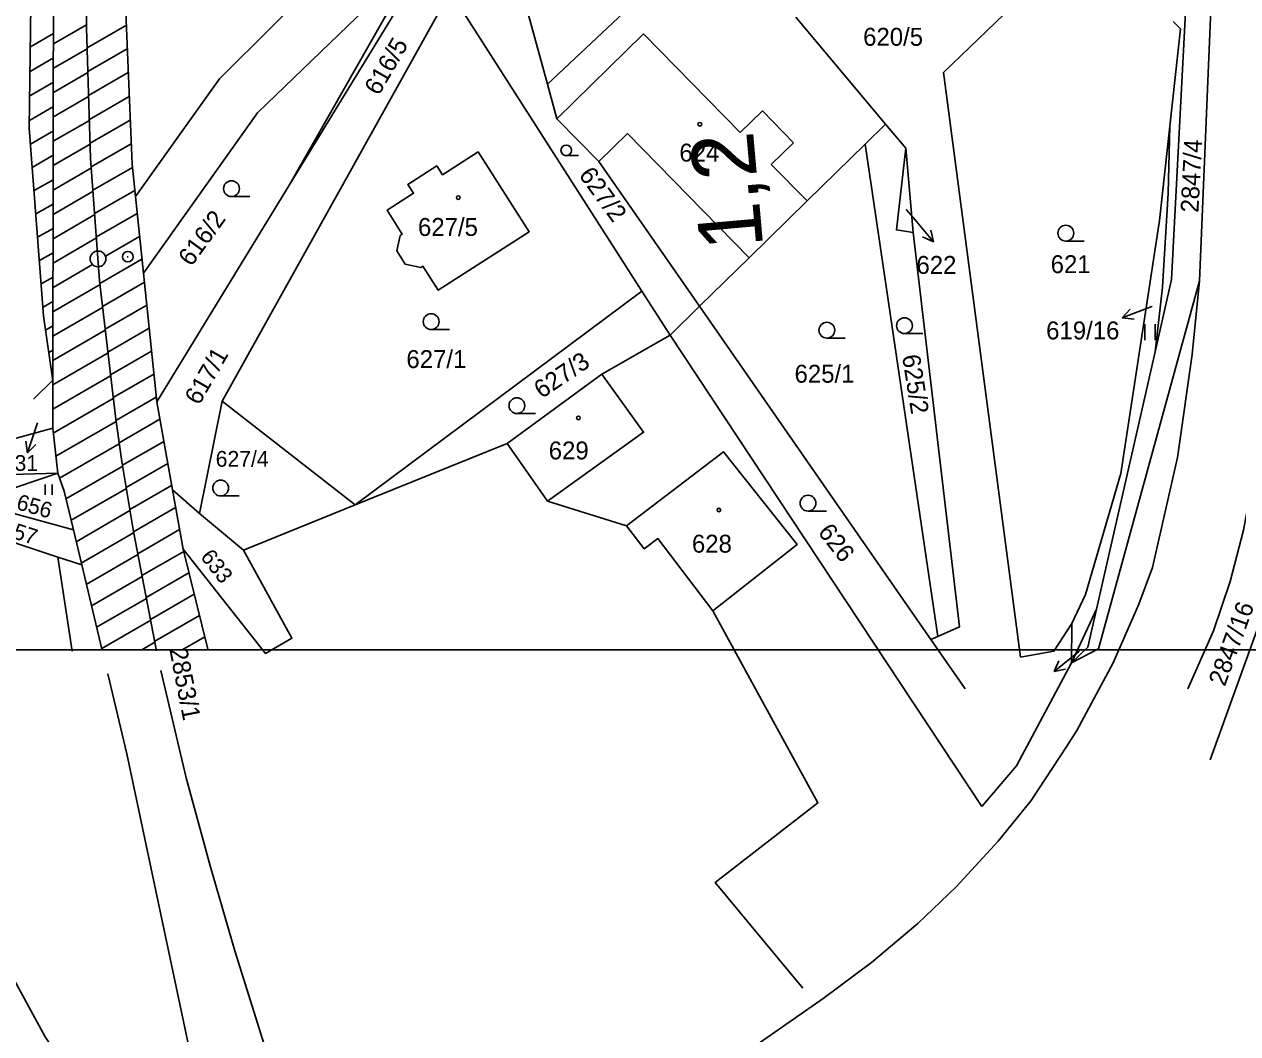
# Model space of a CAD drawing. Extents: x -558500 to -557517, y -1073973 to -1073051.
# Drawn here: x -558299.9 to -558184.7, y -1073820.5 to -1073724.7 of the extents above; entities that cross this region are included whole.
import ezdxf

# ---------------------------------------------------------------- set-up
doc = ezdxf.new("R2010")
doc.units = 0
for name, color, linetype in [('Hranice parcel', 7, 'Continuous'), ('Kolej', 7, 'Continuous'), ('Návěst místo trati', 7, 'Continuous'), ('Parcelní čísla', 7, 'Continuous'), ('Pop  PČ popisy', 7, 'Continuous'), ('Svazek obcí údolí Desné', 7, 'Continuous'), ('Vnitřní kresba', 7, 'Continuous'), ('Vrstva 1', 7, 'Continuous'), ('Značky budov', 7, 'Continuous'), ('Značky kultur', 7, 'Continuous')]:
    doc.layers.add(name, color=color, linetype=linetype)

msp = doc.modelspace()

# ---------------------------------------------------------------- linework, layer by layer
at = {"layer": 'Hranice parcel'}
for p, q in [((-558254.11, -1073716.3), (-558250.26, -1073730.4)), ((-558250.26, -1073730.4), (-558236.6, -1073717.53)), ((-558274.72, -1073739.9), (-558262.39, -1073718.25)), ((-558259.48, -1073721.62), (-558281.15, -1073760.49)), ((-558241.29, -1073750.06), (-558259.48, -1073721.62)), ((-558218.17, -1073734.19), (-558226.69, -1073724.03)), ((-558250.26, -1073730.4), (-558249.36, -1073733.68)), ((-558220.12, -1073736.1), (-558218.17, -1073734.19)), ((-558216.24, -1073736.49), (-558218.17, -1073734.19)), ((-558191.18, -1073734.38), (-558191.35, -1073740.76)), ((-558213.21, -1073782.82), (-558220.12, -1073736.1)), ((-558216.24, -1073736.49), (-558215.54, -1073744.47)), ((-558287.34, -1073760.54), (-558274.72, -1073739.9)), ((-558191.35, -1073740.76), (-558191.89, -1073749.68)), ((-558188.37, -1073749.08), (-558189.08, -1073756.06)), ((-558268.5, -1073770.34), (-558241.29, -1073750.06)), ((-558238.63, -1073754.22), (-558241.29, -1073750.06)), ((-558191.89, -1073749.68), (-558192.59, -1073755.8)), ((-558235.84, -1073751.49), (-558238.63, -1073754.22)), ((-558213.89, -1073783.12), (-558235.84, -1073751.49)), ((-558245.1, -1073757.92), (-558238.63, -1073754.22)), ((-558238.63, -1073754.22), (-558209.02, -1073798.95)), ((-558192.59, -1073755.8), (-558198.14, -1073780.25)), ((-558245.1, -1073757.92), (-558254.1, -1073764.51)), ((-558281.15, -1073760.49), (-558283.28, -1073771.17)), ((-558281.15, -1073760.49), (-558268.5, -1073770.34)), ((-558297.22, -1073763.06), (-558303.78, -1073764.84)), ((-558268.5, -1073770.34), (-558254.1, -1073764.51)), ((-558254.1, -1073764.51), (-558250.25, -1073769.98)), ((-558296.74, -1073767.33), (-558304.84, -1073770.08)), ((-558283.28, -1073771.17), (-558285.85, -1073768.92)), ((-558304.84, -1073770.08), (-558295.26, -1073772.72)), ((-558279.1, -1073774.62), (-558268.5, -1073770.34)), ((-558250.25, -1073769.98), (-558242.76, -1073772.31)), ((-558308.63, -1073771.36), (-558296.72, -1073775.29)), ((-558283.28, -1073771.17), (-558279.1, -1073774.62)), ((-558200.51, -1073785.33), (-558198.14, -1073780.25)), ((-558182.51, -1073781.13), (-558187.36, -1073794.52)), ((-558200.51, -1073785.33), (-558200.5, -1073781.61)), ((-558213.89, -1073783.12), (-558213.21, -1073782.82)), ((-558210.63, -1073787.8), (-558213.89, -1073783.12))]:
    msp.add_line(p, q, dxfattribs=at)
for points in [[(-558289.37, -1073741.07), (-558281.4, -1073729.91), (-558261.12, -1073709.7)], [(-558188.37, -1073749.08), (-558187.04, -1073717.25), (-558187.01, -1073709.55)], [(-558260.45, -1073716.38), (-558262.32, -1073719.63), (-558274.72, -1073739.9)], [(-558189.35, -1073716.89), (-558191.03, -1073748.95), (-558192.59, -1073755.8)], [(-558262.39, -1073718.25), (-558277.79, -1073733.11), (-558288.61, -1073748.35)], [(-558200.5, -1073781.61), (-558202.2, -1073784.23), (-558205.35, -1073784.79), (-558212.68, -1073729.29), (-558206.91, -1073723.76)], [(-558191.18, -1073734.38), (-558190.17, -1073725.16), (-558190.86, -1073724.46)], [(-558189.49, -1073787.81), (-558187.05, -1073782.29), (-558185.46, -1073777.61), (-558184.2, -1073772.75), (-558183.57, -1073769.31), (-558182.51, -1073762.81), (-558181.61, -1073754.21), (-558181.25, -1073749.17), (-558180.93, -1073742.19), (-558180.47, -1073726.64)], [(-558249.36, -1073733.68), (-558245.38, -1073737.75), (-558235.84, -1073751.49)], [(-558200.5, -1073781.61), (-558199.18, -1073778.85), (-558195.83, -1073767.37), (-558192.17, -1073743.33), (-558191.18, -1073734.38)], [(-558235.84, -1073751.49), (-558231.13, -1073746.88), (-558225.62, -1073741.49), (-558220.12, -1073736.1)], [(-558216.24, -1073736.49), (-558217.14, -1073744.24), (-558215.54, -1073744.47)], [(-558264.25, -1073744.77), (-558264.05, -1073744.64), (-558265.49, -1073742.37), (-558262.97, -1073740.76), (-558263.51, -1073739.92), (-558260.77, -1073738.16), (-558260.22, -1073739), (-558256.85, -1073736.83), (-558251.99, -1073744.42), (-558260.65, -1073749.95), (-558262.08, -1073747.68), (-558262.29, -1073747.81), (-558263.76, -1073747.5), (-558264.56, -1073746.23), (-558264.25, -1073744.77)], [(-558213.21, -1073782.82), (-558211.14, -1073781.9), (-558215.54, -1073744.47)], [(-558200.51, -1073785.33), (-558197.97, -1073783.99), (-558188.37, -1073749.08)], [(-558189.08, -1073756.06), (-558190.46, -1073765.85), (-558192.84, -1073776.27), (-558194.14, -1073779.77), (-558196.57, -1073785.34), (-558200.01, -1073791.76), (-558200.97, -1073793.25), (-558204.34, -1073798.41), (-558207.48, -1073802.27), (-558211.47, -1073806.6), (-558215.12, -1073810.07), (-558219.5, -1073813.77), (-558224.1, -1073817.18), (-558263.52, -1073844.66)], [(-558250.25, -1073769.98), (-558241.14, -1073763.44), (-558245.1, -1073757.92)], [(-558242.76, -1073772.31), (-558233.55, -1073765.31), (-558226.57, -1073774.11), (-558234.56, -1073780.4)], [(-558314.07, -1073773.21), (-558306.66, -1073767.6), (-558296.74, -1073767.33)], [(-558242.76, -1073772.31), (-558241.08, -1073774.51), (-558239.8, -1073773.53), (-558234.56, -1073780.4)], [(-558279.1, -1073774.62), (-558274.51, -1073783), (-558277.02, -1073784.45), (-558284.85, -1073774.53)], [(-558278.21, -1073850.5), (-558297.93, -1073820.82), (-558309.88, -1073798.91), (-558319.99, -1073775.22)], [(-558198.14, -1073780.25), (-558198.96, -1073783.85), (-558200.51, -1073785.33)], [(-558234.56, -1073780.4), (-558224.59, -1073798.63), (-558234.34, -1073806.17), (-558226.01, -1073816.21)], [(-558209.02, -1073798.95), (-558205.75, -1073795.1), (-558200.51, -1073785.33)]]:
    msp.add_lwpolyline(points, dxfattribs=at)
at = {"layer": 'Kolej'}
for points in [[(-558287.36, -1073784.19), (-558289.56, -1073772.87), (-558290.66, -1073766.21), (-558291.24, -1073762.21), (-558292.77, -1073749.06), (-558293.62, -1073737.47), (-558294.02, -1073725.05), (-558293.93, -1073713.18), (-558293.34, -1073701.02), (-558292.27, -1073689.01), (-558290.77, -1073677.31), (-558288.8, -1073665.65)], [(-558265.5, -1073858.14), (-558266.34, -1073855.54), (-558269.72, -1073844.91), (-558271.89, -1073838.13), (-558274.8, -1073829.01), (-558277.32, -1073821.06), (-558279.92, -1073812.66), (-558282.28, -1073804.61), (-558284.55, -1073796.24), (-558286.95, -1073786.06)]]:
    msp.add_lwpolyline(points, dxfattribs=at)
at = {"layer": 'Návěst místo trati'}
msp.add_line((-558290.15, -1073746.78), (-558290.05, -1073746.78), dxfattribs=at)
for centre, radius in [((-558292.92, -1073746.99), 0.75), ((-558290.09, -1073746.78), 0.5)]:
    msp.add_circle(centre, radius, dxfattribs=at)
at = {"layer": 'Pop  PČ popisy'}
for p, q in [((-558216.21, -1073742.3), (-558215.56, -1073743.06)), ((-558215.56, -1073743.06), (-558213.63, -1073745.36)), ((-558213.63, -1073745.36), (-558213.89, -1073744.27)), ((-558213.63, -1073745.36), (-558214.66, -1073744.91)), ((-558192.9, -1073751.52), (-558195.7, -1073752.59)), ((-558195.7, -1073752.59), (-558194.95, -1073751.77)), ((-558195.7, -1073752.59), (-558194.59, -1073752.7)), ((-558192.88, -1073751.51), (-558192.9, -1073751.52)), ((-558298.67, -1073762.56), (-558299.62, -1073765.4)), ((-558299.62, -1073765.4), (-558299.78, -1073764.29)), ((-558299.62, -1073765.4), (-558298.83, -1073764.61)), ((-558199.85, -1073784.27), (-558202.18, -1073786.16)), ((-558199.56, -1073784.03), (-558199.85, -1073784.27)), ((-558202.18, -1073786.16), (-558201.72, -1073785.14)), ((-558202.18, -1073786.16), (-558201.09, -1073785.92))]:
    msp.add_line(p, q, dxfattribs=at)
at = {"layer": 'Svazek obcí údolí Desné'}
for p, q in [((-558297.15, -1073726.57), (-558294.02, -1073724.77)), ((-558293.96, -1073726.95), (-558290.23, -1073724.79)), ((-558299.34, -1073726.86), (-558297.15, -1073725.59)), ((-558297.15, -1073728.89), (-558293.96, -1073727.04)), ((-558293.89, -1073729.21), (-558290.14, -1073727.05)), ((-558299.37, -1073729.19), (-558297.15, -1073727.91)), ((-558297.16, -1073731.2), (-558293.88, -1073729.31)), ((-558293.81, -1073731.48), (-558290.05, -1073729.31)), ((-558299.4, -1073731.51), (-558297.16, -1073730.22)), ((-558297.16, -1073733.51), (-558293.81, -1073731.57)), ((-558293.74, -1073733.75), (-558289.95, -1073731.56)), ((-558299.43, -1073733.84), (-558297.16, -1073732.53)), ((-558297.17, -1073735.82), (-558293.74, -1073733.84)), ((-558293.67, -1073736.01), (-558289.86, -1073733.82)), ((-558299.32, -1073736.09), (-558297.16, -1073734.84)), ((-558297.17, -1073738.13), (-558293.66, -1073736.11)), ((-558293.56, -1073738.26), (-558289.77, -1073736.07)), ((-558299.16, -1073738.3), (-558297.17, -1073737.15)), ((-558297.18, -1073740.45), (-558293.55, -1073738.35)), ((-558293.4, -1073740.48), (-558289.66, -1073738.32)), ((-558298.99, -1073740.51), (-558297.17, -1073739.47)), ((-558297.18, -1073742.76), (-558293.39, -1073740.57)), ((-558293.24, -1073742.69), (-558289.43, -1073740.5)), ((-558289.37, -1073741.07), (-558288.61, -1073748.35)), ((-558298.82, -1073742.72), (-558297.18, -1073741.78)), ((-558297.18, -1073745.07), (-558293.23, -1073742.79)), ((-558293.07, -1073744.91), (-558289.2, -1073742.67)), ((-558298.65, -1073744.94), (-558297.18, -1073744.09)), ((-558297.19, -1073747.38), (-558293.07, -1073745)), ((-558292.22, -1073746.73), (-558288.98, -1073744.85)), ((-558298.48, -1073747.15), (-558297.19, -1073746.4)), ((-558297.19, -1073749.69), (-558293.44, -1073747.53)), ((-558292.74, -1073749.33), (-558288.75, -1073747.03)), ((-558298.31, -1073749.36), (-558297.19, -1073748.71)), ((-558288.61, -1073748.35), (-558287.34, -1073760.54)), ((-558297.2, -1073752.01), (-558292.73, -1073749.42)), ((-558292.49, -1073751.5), (-558288.52, -1073749.21)), ((-558298.14, -1073751.57), (-558297.2, -1073751.03)), ((-558292.24, -1073753.66), (-558288.29, -1073751.39)), ((-558297.21, -1073758.56), (-558298.08, -1073752.4)), ((-558297.2, -1073754.32), (-558292.48, -1073751.59)), ((-558297.89, -1073753.74), (-558297.2, -1073753.34)), ((-558297.21, -1073756.63), (-558292.23, -1073753.75)), ((-558291.98, -1073755.83), (-558288.07, -1073753.57)), ((-558297.59, -1073755.87), (-558297.2, -1073755.65)), ((-558297.21, -1073758.94), (-558291.97, -1073755.92)), ((-558291.73, -1073757.99), (-558287.84, -1073755.74)), ((-558297.29, -1073758.01), (-558297.21, -1073757.96)), ((-558297.22, -1073761.25), (-558291.72, -1073758.08)), ((-558291.48, -1073760.16), (-558287.61, -1073757.92)), ((-558297.21, -1073758.56), (-558297.22, -1073763.06)), ((-558297.17, -1073763.53), (-558291.47, -1073760.25)), ((-558291.23, -1073762.32), (-558287.39, -1073760.1)), ((-558287.34, -1073760.54), (-558285.85, -1073768.92)), ((-558296.92, -1073765.7), (-558291.21, -1073762.41)), ((-558290.91, -1073764.45), (-558287.04, -1073762.21)), ((-558297.22, -1073763.06), (-558296.74, -1073767.33)), ((-558296.57, -1073767.81), (-558290.9, -1073764.54)), ((-558290.59, -1073766.57), (-558286.67, -1073764.31)), ((-558290.25, -1073768.68), (-558286.3, -1073766.4)), ((-558295.96, -1073769.77), (-558290.58, -1073766.66)), ((-558295.48, -1073771.8), (-558290.23, -1073768.77)), ((-558289.9, -1073770.79), (-558285.93, -1073768.5)), ((-558285.85, -1073768.92), (-558284.85, -1073774.53)), ((-558295, -1073773.83), (-558289.89, -1073770.88)), ((-558289.55, -1073772.9), (-558285.55, -1073770.59)), ((-558295.26, -1073772.72), (-558294.47, -1073776.03)), ((-558294.51, -1073775.86), (-558289.54, -1073772.99)), ((-558289.15, -1073774.98), (-558285.18, -1073772.68)), ((-558284.85, -1073774.53), (-558282.46, -1073784.17)), ((-558296.72, -1073775.29), (-558294.47, -1073776.03)), ((-558294.03, -1073777.89), (-558289.13, -1073775.06)), ((-558288.75, -1073777.05), (-558284.79, -1073774.77)), ((-558288.34, -1073779.13), (-558284.29, -1073776.79)), ((-558293.54, -1073779.92), (-558288.73, -1073777.14)), ((-558287.94, -1073781.2), (-558283.79, -1073778.81)), ((-558293.06, -1073781.95), (-558288.33, -1073779.22)), ((-558292.57, -1073783.98), (-558287.92, -1073781.29)), ((-558287.54, -1073783.28), (-558283.29, -1073780.83)), ((-558288.77, -1073784.09), (-558287.52, -1073783.37)), ((-558284.93, -1073784.09), (-558282.78, -1073782.85))]:
    msp.add_line(p, q, dxfattribs=at)
for points in [[(-558237.23, -1073540.41), (-558250.35, -1073559.71), (-558264.4, -1073584.99), (-558277.08, -1073613.49), (-558283.33, -1073632.3), (-558290.3, -1073658.29), (-558296.01, -1073700.28), (-558297.13, -1073716.84), (-558297.21, -1073758.56)], [(-558287.25, -1073676.53), (-558288.33, -1073687.34), (-558288.98, -1073695.83), (-558290.03, -1073705.01), (-558290.44, -1073719.74), (-558289.69, -1073738.01), (-558289.37, -1073741.07)], [(-558298.08, -1073752.4), (-558299.44, -1073734.57), (-558299.09, -1073706.57)], [(-558296.74, -1073767.33), (-558296.14, -1073769.02), (-558295.26, -1073772.72)], [(-558295.36, -1073784.21), (-558296.72, -1073775.29)], [(-558294.47, -1073776.03), (-558292.53, -1073784.17)], [(-558292, -1073786.37), (-558290.19, -1073793.95), (-558283.32, -1073826.38)]]:
    msp.add_lwpolyline(points, dxfattribs=at)
at = {"layer": 'Vnitřní kresba'}
for p, q in [((-558249.36, -1073733.68), (-558241.14, -1073725.64)), ((-558241.14, -1073725.64), (-558231.97, -1073735)), ((-558231.97, -1073735), (-558229.86, -1073732.94)), ((-558229.86, -1073732.94), (-558226.91, -1073735.96)), ((-558245.38, -1073737.75), (-558242.66, -1073735.09)), ((-558242.66, -1073735.09), (-558231.13, -1073746.88)), ((-558229.02, -1073738.02), (-558226.91, -1073735.96)), ((-558229.02, -1073738.02), (-558225.62, -1073741.49))]:
    msp.add_line(p, q, dxfattribs=at)
at = {"layer": 'Vrstva 1'}
for p, q in [((-558298.14, -1073752.46), (-558298.07, -1073752.46)), ((-558299.04, -1073760.31), (-558297.22, -1073758.49)), ((-557516.53, -1073784.09), (-558357.53, -1073784.09))]:
    msp.add_line(p, q, dxfattribs=at)
at = {"layer": 'Značky budov'}
for centre in [(-558235.8, -1073734.21), (-558258.73, -1073741.17), (-558247.32, -1073762.08), (-558233.99, -1073770.82)]:
    msp.add_circle(centre, 0.175, dxfattribs=at)
at = {"layer": 'Značky kultur'}
for p, q in [((-558248.47, -1073737.19), (-558247.3, -1073737.19)), ((-558280.25, -1073741.08), (-558278.5, -1073741.08)), ((-558201.06, -1073745.3), (-558199.31, -1073745.3)), ((-558261.31, -1073753.69), (-558259.56, -1073753.69)), ((-558193.57, -1073754.69), (-558193.57, -1073753.19)), ((-558192.57, -1073754.69), (-558192.57, -1073753.19)), ((-558223.74, -1073754.51), (-558221.99, -1073754.51)), ((-558216.38, -1073754.08), (-558214.63, -1073754.08)), ((-558253.16, -1073761.67), (-558251.41, -1073761.67)), ((-558297.93, -1073769.39), (-558297.93, -1073768.39)), ((-558297.26, -1073769.39), (-558297.26, -1073768.39)), ((-558281.28, -1073769.49), (-558279.53, -1073769.49)), ((-558225.53, -1073770.92), (-558223.78, -1073770.92))]:
    msp.add_line(p, q, dxfattribs=at)
for centre, radius in [((-558248.48, -1073736.69), 0.502), ((-558280.25, -1073740.33), 0.75), ((-558201.06, -1073744.55), 0.75), ((-558261.3, -1073752.94), 0.75), ((-558216.38, -1073753.33), 0.75), ((-558223.74, -1073753.76), 0.75), ((-558253.16, -1073760.92), 0.75), ((-558281.28, -1073768.74), 0.75), ((-558225.53, -1073770.17), 0.75)]:
    msp.add_circle(centre, radius, dxfattribs=at)

# ---------------------------------------------------------------- texts
at = {"layer": 'Návěst místo trati'}
msp.add_text('1,2', height=6, rotation=95.054, dxfattribs=at).set_placement((-558229.78, -1073745.86))
at = {"layer": 'Parcelní čísla'}
for s, height, p in [('620/5', 1.7, (-558220.3, -1073726.76)), ('624', 1.7, (-558237.74, -1073737.75)), ('627/5', 1.7, (-558262.55, -1073744.81)), ('622', 1.7, (-558215.24, -1073748.41)), ('621', 1.7, (-558202.5, -1073748.34)), ('619/16', 1.7, (-558202.93, -1073754.63)), ('627/1', 1.7, (-558263.65, -1073757.35)), ('625/1', 1.7, (-558226.81, -1073758.74)), ('627/4', 1.5, (-558281.75, -1073766.72)), ('629', 1.7, (-558250.14, -1073766.02)), ('2502/31', 1.5, (-558305.86, -1073767.11)), ('628', 1.7, (-558236.55, -1073774.87))]:
    msp.add_text(s, height=height, dxfattribs=at).set_placement(p)
for s, height, rotation, p in [('616/5', 1.7, 60, (-558266.27, -1073731.57)), ('2847/4', 1.7, 87, (-558188.48, -1073742.63)), ('627/2', 1.7, 306, (-558247.35, -1073739.04)), ('616/2', 1.7, 54, (-558284.06, -1073747.79)), ('617/1', 1.7, 60, (-558283.33, -1073760.96)), ('627/3', 1.7, 34, (-558250.81, -1073760.3)), ('625/2', 1.7, 279, (-558216.61, -1073756.19)), ('656', 1.5, 344, (-558300.76, -1073770.72)), ('657', 1.5, 342, (-558302.15, -1073773.13)), ('626', 1.7, 308, (-558224.66, -1073772.94)), ('633', 1.5, 308, (-558283.26, -1073775.29)), ('2847/16', 1.7, 70, (-558185.97, -1073787.64))]:
    msp.add_text(s, height=height, rotation=rotation, dxfattribs=at).set_placement(p)
at = {"layer": 'Vrstva 1'}
msp.add_text('2853/1', height=1.7, rotation=281, dxfattribs=at).set_placement((-558286.15, -1073784.07))

doc.saveas('drawing.dxf')
